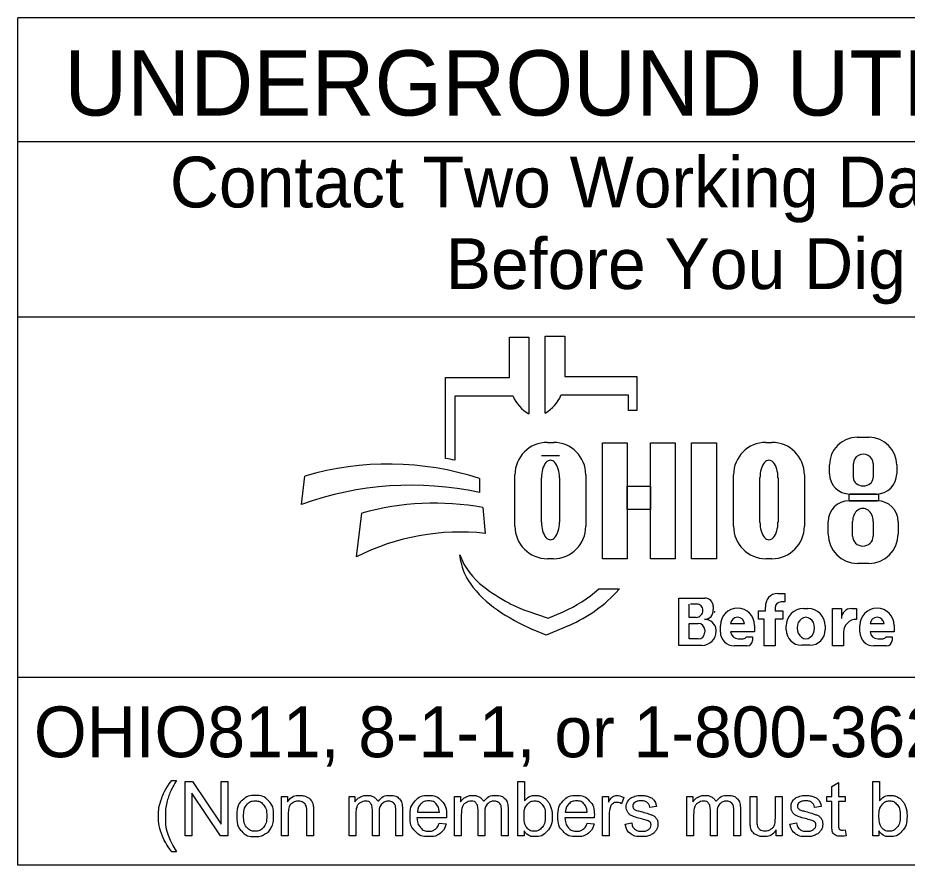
# Model space of a CAD drawing. Extents: x 39.5 to 73.5, y 15.6 to 37.6.
# Drawn here: x 42.479 to 44.932, y 18.55 to 20.887 of the extents above; entities that cross this region are included whole.
import ezdxf

# ---------------------------------------------------------------- set-up
doc = ezdxf.new("R2010")
doc.units = 0
doc.layers.add('GM_X_Interstate_Route', color=7, linetype='Continuous')
doc.layers.add('GM_X_Major_River_Text', color=7, linetype='Continuous')

msp = doc.modelspace()

# ---------------------------------------------------------------- linework, layer by layer
at = {"layer": 'GM_X_Interstate_Route'}
for p, q in [((43.8348, 19.8955), (43.8348, 20.0069)), ((43.8348, 20.0069), (43.8884, 20.0069)), ((43.8884, 20.0069), (43.8884, 19.7949)), ((43.9341, 19.7972), (43.9341, 20.0093)), ((43.9341, 20.0093), (43.9877, 20.0093)), ((43.9877, 20.0093), (43.9877, 19.8978)), ((43.6588, 19.6716), (43.6588, 19.8955)), ((43.6588, 19.8955), (43.8348, 19.8955)), ((43.9877, 19.8978), (44.187, 19.8978)), ((44.187, 19.8978), (44.187, 19.804)), ((43.684, 19.844), (43.684, 19.6672)), ((43.8452, 19.844), (43.684, 19.844)), ((44.1637, 19.8463), (43.9773, 19.8463)), ((44.1637, 19.804), (44.1637, 19.8463)), ((44.187, 19.804), (44.1637, 19.804)), ((44.7943, 19.7303), (44.8271, 19.7303)), ((43.9397, 19.7163), (43.9563, 19.7163)), ((44.5428, 19.7163), (44.5593, 19.7163)), ((43.973, 19.6793), (43.9232, 19.6793)), ((44.7842, 19.6183), (44.7842, 19.6576)), ((44.8383, 19.6576), (44.8383, 19.6183)), ((44.718, 19.6297), (44.718, 19.654)), ((44.9034, 19.654), (44.9034, 19.6297)), ((43.2614, 19.5453), (43.2708, 19.6234)), ((43.7521, 19.6169), (43.7521, 19.5781)), ((43.8503, 19.4848), (43.8503, 19.6268)), ((43.9232, 19.4962), (43.9232, 19.6185)), ((43.973, 19.6185), (43.973, 19.4962)), ((44.0458, 19.6268), (44.0458, 19.4848)), ((44.4533, 19.4848), (44.4533, 19.6268)), ((44.5262, 19.4962), (44.5262, 19.6185)), ((44.576, 19.6185), (44.576, 19.4962)), ((44.6488, 19.6268), (44.6488, 19.4848)), ((44.8474, 19.5737), (44.774, 19.5737)), ((43.7621, 19.5363), (43.7683, 19.4653)), ((44.7722, 19.5554), (44.8495, 19.5554)), ((43.4133, 19.4007), (43.4279, 19.5209)), ((44.7143, 19.4634), (44.7143, 19.4975)), ((44.7818, 19.4575), (44.7818, 19.4984)), ((44.8387, 19.4984), (44.8387, 19.4575)), ((44.9074, 19.4975), (44.9074, 19.4634)), ((43.7009, 19.3878), (43.6979, 19.4058)), ((43.9563, 19.3953), (43.9397, 19.3953)), ((44.5593, 19.3953), (44.5428, 19.3953)), ((44.8265, 19.3825), (44.7953, 19.3825)), ((44.0812, 19.312), (44.1387, 19.312)), ((44.3025, 19.1562), (44.3025, 19.2869)), ((44.3025, 19.2869), (44.3737, 19.2869)), ((44.5751, 19.2997), (44.5946, 19.2997)), ((44.5946, 19.2997), (44.5946, 19.2767)), ((44.3305, 19.2334), (44.3305, 19.2704)), ((44.3557, 19.2704), (44.3344, 19.2704)), ((44.3975, 19.2632), (44.3975, 19.2553)), ((44.5946, 19.2763), (44.5844, 19.2763)), ((43.8828, 19.2516), (43.9422, 19.2311)), ((43.9422, 19.2311), (43.9833, 19.2489)), ((44.5225, 19.2284), (44.5225, 19.2513)), ((44.5225, 19.2513), (44.5418, 19.2513)), ((44.5418, 19.2513), (44.5418, 19.2618)), ((44.5679, 19.2598), (44.5679, 19.2513)), ((44.5679, 19.2513), (44.5895, 19.2513)), ((44.5895, 19.2513), (44.5895, 19.2284)), ((44.6463, 19.2579), (44.6585, 19.2579)), ((44.7266, 19.155), (44.7266, 19.2577)), ((44.7266, 19.2577), (44.7511, 19.2577)), ((44.7511, 19.2577), (44.7511, 19.2308)), ((44.7784, 19.2577), (44.7923, 19.2577)), ((44.7923, 19.2577), (44.7923, 19.228)), ((44.3499, 19.2334), (44.3305, 19.2334)), ((44.3305, 19.174), (44.3305, 19.2169)), ((44.3305, 19.2169), (44.356, 19.2169)), ((44.4837, 19.2154), (44.4451, 19.2154)), ((44.5374, 19.2284), (44.5225, 19.2284)), ((44.5374, 19.155), (44.5374, 19.2284)), ((44.5895, 19.2284), (44.5679, 19.2284)), ((44.5679, 19.2284), (44.5679, 19.155)), ((44.8686, 19.2154), (44.8301, 19.2154)), ((43.9362, 19.1841), (43.8989, 19.2005)), ((43.9995, 19.2115), (43.9362, 19.1841)), ((44.3742, 19.1988), (44.3742, 19.1924)), ((44.4055, 19.1959), (44.4055, 19.1955)), ((44.4171, 19.193), (44.4171, 19.2114)), ((44.5116, 19.1937), (44.4452, 19.1937)), ((44.5116, 19.2114), (44.5116, 19.1937)), ((44.5985, 19.1993), (44.5985, 19.2101)), ((44.7063, 19.2101), (44.7063, 19.1993)), ((44.7571, 19.1931), (44.7571, 19.155)), ((44.802, 19.193), (44.802, 19.2114)), ((44.8965, 19.1937), (44.8301, 19.1937)), ((44.8965, 19.2114), (44.8965, 19.1937)), ((44.3558, 19.174), (44.3305, 19.174)), ((44.4661, 19.1745), (44.4802, 19.1745)), ((44.4888, 19.18), (44.5057, 19.18)), ((44.5057, 19.18), (44.5057, 19.1702)), ((44.851, 19.1745), (44.8652, 19.1745)), ((44.8737, 19.18), (44.8906, 19.18)), ((44.8906, 19.18), (44.8906, 19.1702)), ((44.3662, 19.1562), (44.3025, 19.1562)), ((44.4904, 19.155), (44.455, 19.155)), ((44.5679, 19.155), (44.5374, 19.155)), ((44.6635, 19.1565), (44.6413, 19.1565)), ((44.7571, 19.155), (44.7266, 19.155)), ((44.8754, 19.155), (44.84, 19.155))]:
    msp.add_line(p, q, dxfattribs=at)
for points in [[(44.0922, 19.7152), (44.1601, 19.7152), (44.1601, 19.3952), (44.0922, 19.3952)], [(44.2243, 19.7152), (44.2923, 19.7152), (44.2923, 19.3952), (44.2243, 19.3952)], [(44.3376, 19.7152), (44.4064, 19.7152), (44.4064, 19.3952), (44.3376, 19.3952)], [(44.1601, 19.5953), (44.2243, 19.5953), (44.2243, 19.5313), (44.1601, 19.5313)], [(44.7719, 19.5737), (44.8535, 19.5737), (44.8535, 19.5552), (44.7719, 19.5552)]]:
    msp.add_lwpolyline(points, close=True, dxfattribs=at)
for points in [[(42.9033, 18.7837), (42.9165, 18.7837)], [(42.9401, 18.6311), (42.9401, 18.7812), (42.9604, 18.7812), (43.0394, 18.6633), (43.0394, 18.7812), (43.0584, 18.7812), (43.0584, 18.6311), (43.0381, 18.6311), (42.9591, 18.749), (42.9591, 18.6311), (42.9401, 18.6311)], [(43.8755, 18.6311), (43.8585, 18.6311), (43.8585, 18.7812), (43.8769, 18.7812), (43.8769, 18.7277)], [(44.7245, 18.6629), (44.7245, 18.7256), (44.7109, 18.7256), (44.7109, 18.7399), (44.7245, 18.7399), (44.7245, 18.7669), (44.7429, 18.7779), (44.7429, 18.7399), (44.7613, 18.7399), (44.7613, 18.7256), (44.7429, 18.7256), (44.7429, 18.6618)], [(44.8546, 18.6311), (44.8376, 18.6311), (44.8376, 18.7812), (44.856, 18.7812), (44.856, 18.7277)], [(43.206, 18.6311), (43.206, 18.7399), (43.2226, 18.7399), (43.2226, 18.7244)], [(43.3925, 18.6311), (43.3925, 18.7399), (43.4089, 18.7399), (43.4089, 18.7246)], [(43.6838, 18.6311), (43.6838, 18.7399), (43.7003, 18.7399), (43.7003, 18.7246)], [(44.0916, 18.6311), (44.0916, 18.7399), (44.1082, 18.7399), (44.1082, 18.7234)], [(44.1507, 18.7364), (44.1442, 18.7194)], [(44.3248, 18.6311), (44.3248, 18.7399), (44.3413, 18.7399), (44.3413, 18.7246)], [(44.4991, 18.6725), (44.4991, 18.7399), (44.5176, 18.7399), (44.5176, 18.6796)], [(44.5688, 18.6816), (44.5688, 18.7399), (44.5873, 18.7399), (44.5873, 18.6311), (44.5708, 18.6311)], [(43.2944, 18.698), (43.2944, 18.6311), (43.276, 18.6311), (43.276, 18.6972)], [(43.4755, 18.6942), (43.4755, 18.6311), (43.4571, 18.6311), (43.4571, 18.7017)], [(43.54, 18.7057), (43.54, 18.6311), (43.5215, 18.6311), (43.5215, 18.6996)], [(43.7669, 18.6942), (43.7669, 18.6311), (43.7485, 18.6311), (43.7485, 18.7017)], [(43.8313, 18.7057), (43.8313, 18.6311), (43.8129, 18.6311), (43.8129, 18.6996)], [(44.2406, 18.7118), (44.2225, 18.7094)], [(44.4079, 18.6942), (44.4079, 18.6311), (44.3895, 18.6311), (44.3895, 18.7017)], [(44.4723, 18.7057), (44.4723, 18.6311), (44.4539, 18.6311), (44.4539, 18.6996)], [(44.6952, 18.7118), (44.6771, 18.7094)], [(43.2245, 18.6905), (43.2245, 18.6311), (43.206, 18.6311)], [(43.4109, 18.6875), (43.4109, 18.6311), (43.3925, 18.6311)], [(43.6612, 18.6807), (43.58, 18.6807)], [(43.5811, 18.6959), (43.6418, 18.6959)], [(43.7023, 18.6875), (43.7023, 18.6311), (43.6838, 18.6311)], [(44.0692, 18.6807), (43.988, 18.6807)], [(43.9891, 18.6959), (44.0498, 18.6959)], [(44.11, 18.6881), (44.11, 18.6311), (44.0916, 18.6311)], [(44.3433, 18.6875), (44.3433, 18.6311), (44.3248, 18.6311)], [(43.6416, 18.6662), (43.6607, 18.6638)], [(44.0496, 18.6662), (44.0687, 18.6638)], [(44.1542, 18.6636), (44.1724, 18.6664)], [(44.6088, 18.6636), (44.627, 18.6664)], [(43.8755, 18.6447), (43.8755, 18.6311)], [(44.5708, 18.6311), (44.5708, 18.6471)], [(44.7613, 18.6475), (44.764, 18.6312)], [(44.8546, 18.6447), (44.8546, 18.6311)], [(42.9165, 18.5869), (42.9033, 18.5869)]]:
    msp.add_lwpolyline(points, dxfattribs=at)
for centre, radius, start, end in [((43.9365, 19.8808), 0.0985, 201.9296, 240.7469), ((43.8859, 19.8831), 0.0985, 299.2531, 338.0704), ((44.7943, 19.654), 0.0763, 90, 180), ((44.8271, 19.654), 0.0763, 0, 90), ((43.9397, 19.6268), 0.0895, 90, 180), ((43.9563, 19.6268), 0.0895, 0, 90), ((44.5428, 19.6268), 0.0895, 90, 180), ((44.5593, 19.6268), 0.0895, 0, 90), ((43.5009, 18.8373), 0.8191, 72.1402, 106.3144), ((43.5307, 18.8626), 0.8191, 79.2074, 81.0007), ((44.774, 19.6297), 0.056, 180, 270), ((44.8474, 19.6297), 0.056, 270, 0), ((43.564, 18.7062), 0.8919, 77.8238, 109.8274), ((43.6279, 18.8165), 0.7322, 79.44, 105.8467), ((44.7722, 19.4975), 0.0579, 90, 180), ((44.8495, 19.4975), 0.0579, 0, 90), ((43.9397, 19.4848), 0.0895, 180, 270), ((43.9563, 19.4848), 0.0895, 270, 0), ((44.5428, 19.4848), 0.0895, 180, 270), ((44.5593, 19.4848), 0.0895, 270, 0), ((43.6999, 18.8333), 0.6357, 83.8248, 116.8021), ((44.7953, 19.4634), 0.081, 180, 270), ((44.8265, 19.4634), 0.081, 270, 0), ((43.8853, 19.4779), 0.2008, 201.0457, 232.5314), ((43.8422, 19.4119), 0.1433, 189.6817, 216.0884), ((43.9759, 19.5094), 0.3088, 216.0884, 235.7167), ((44.0778, 19.7291), 0.5173, 232.5314, 241.794), ((43.8399, 19.5794), 0.3602, 293.4582, 312.0712), ((43.8399, 19.5794), 0.401, 293.4582, 317.8286), ((44.3737, 19.2632), 0.0238, 0, 90), ((44.5751, 19.2662), 0.0335, 90, 187.5187), ((43.9926, 19.5703), 0.3371, 241.794, 250.9821), ((44.3518, 19.2535), 0.0169, 357.8325, 90), ((44.5844, 19.2598), 0.0165, 90, 180), ((44.1424, 19.7536), 0.6044, 235.7167, 246.2325), ((44.3499, 19.2522), 0.0187, 270, 2.0582), ((44.3733, 19.2524), 0.0243, 270, 6.6529), ((44.3839, 19.251), 0.0175, 347.4023, 0), ((44.4643, 19.2114), 0.0473, 0, 180), ((44.6463, 19.2101), 0.0478, 90, 180), ((44.6585, 19.2101), 0.0478, 0, 90), ((44.778, 19.2308), 0.0269, 89.2449, 180), ((44.8493, 19.2114), 0.0473, 0, 180), ((44.356, 19.1988), 0.0181, 0, 90), ((44.3734, 19.196), 0.0321, 4.0748, 90), ((44.4644, 19.2144), 0.0193, 2.9632, 177.0368), ((44.792, 19.1931), 0.0349, 89.6033, 180), ((44.8493, 19.2144), 0.0193, 2.9632, 177.0368), ((44.3558, 19.1924), 0.0184, 270, 0), ((44.3662, 19.1955), 0.0393, 270, 0), ((44.3726, 19.1959), 0.033, 0, 11.7502), ((44.455, 19.193), 0.038, 180, 270), ((44.4661, 19.1955), 0.021, 184.827, 270), ((44.6413, 19.1993), 0.0428, 180, 270), ((44.6635, 19.1993), 0.0428, 270, 0), ((44.84, 19.193), 0.038, 180, 270), ((44.851, 19.1955), 0.021, 184.827, 270), ((44.4802, 19.1839), 0.00938, 270, 335.9979), ((44.4904, 19.1702), 0.0152, 270, 0), ((44.8652, 19.1839), 0.00938, 270, 335.9979), ((44.8754, 19.1702), 0.0152, 270, 0)]:
    msp.add_arc(centre, radius, start, end, dxfattribs=at)
for centre, major_axis, ratio, start_param, end_param in [((44.8112, 19.6576), (0.0271, 0), 0.969373, 0, 3.141593), ((43.9481, 19.6185), (0, 0.0484), 0.514403, 4.712389, 7.853982), ((44.5511, 19.6185), (0, 0.0484), 0.514403, 4.712389, 7.853982), ((44.8112, 19.6183), (0.0271, 0), 0.818453, 3.141593, 6.283185), ((44.8102, 19.4984), (0, 0.0358), 0.794529, 4.712389, 7.853982), ((43.9481, 19.4962), (0, 0.0484), 0.514403, 1.570796, 4.712389), ((44.5511, 19.4962), (0, 0.0484), 0.514403, 1.570796, 4.712389), ((44.8102, 19.4575), (0.0284, 0), 0.959837, 3.141593, 6.283185), ((44.6529, 19.2047), (0, 0.029), 0.832186, 4.712389, 7.853982), ((44.6529, 19.2047), (0, 0.0302), 0.797287, 1.570796, 4.712389)]:
    msp.add_ellipse(centre, major_axis=major_axis, ratio=ratio, start_param=start_param, end_param=end_param, dxfattribs=at)
for points in [[(42.9033, 18.5869), (42.8881, 18.6062), (42.8775, 18.632), (42.8669, 18.6578), (42.8669, 18.6854), (42.8669, 18.7098), (42.8748, 18.7321), (42.8841, 18.758), (42.9033, 18.7837)], [(42.9165, 18.7837), (42.9041, 18.7624), (42.9002, 18.7533), (42.8939, 18.7392), (42.8903, 18.7238), (42.8859, 18.7047), (42.8859, 18.6853), (42.8859, 18.6361), (42.9165, 18.5869)], [(43.0826, 18.6855), (43.0826, 18.7157), (43.0993, 18.7302), (43.1134, 18.7423), (43.1335, 18.7423), (43.156, 18.7423), (43.1702, 18.7276), (43.1844, 18.7129), (43.1844, 18.687), (43.1844, 18.666), (43.1781, 18.654), (43.1718, 18.642), (43.1598, 18.6353), (43.1478, 18.6287), (43.1335, 18.6287), (43.1107, 18.6287), (43.0966, 18.6433), (43.0826, 18.658), (43.0826, 18.6855)], [(43.1016, 18.6855), (43.1016, 18.6646), (43.1107, 18.6542), (43.1197, 18.6438), (43.1335, 18.6438), (43.1472, 18.6438), (43.1563, 18.6542), (43.1654, 18.6647), (43.1654, 18.6861), (43.1654, 18.7063), (43.1563, 18.7167), (43.1471, 18.7271), (43.1335, 18.7271), (43.1197, 18.7271), (43.1107, 18.7167), (43.1016, 18.7064), (43.1016, 18.6855)], [(43.2226, 18.7244), (43.2346, 18.7423), (43.2572, 18.7423), (43.2671, 18.7423), (43.2753, 18.7388), (43.2835, 18.7352), (43.2876, 18.7295), (43.2917, 18.7238), (43.2934, 18.7159), (43.2944, 18.7108), (43.2944, 18.698)], [(43.276, 18.6972), (43.276, 18.7085), (43.2738, 18.7141), (43.2717, 18.7196), (43.2662, 18.723), (43.2607, 18.7263), (43.2533, 18.7263), (43.2416, 18.7263), (43.233, 18.7188), (43.2245, 18.7113), (43.2245, 18.6905)], [(43.4089, 18.7246), (43.4141, 18.7326), (43.4226, 18.7374), (43.4311, 18.7423), (43.4419, 18.7423), (43.454, 18.7423), (43.4618, 18.7373), (43.4695, 18.7323), (43.4727, 18.7232), (43.4856, 18.7423), (43.5063, 18.7423), (43.5225, 18.7423), (43.5313, 18.7334), (43.54, 18.7244), (43.54, 18.7057)], [(43.4571, 18.7017), (43.4571, 18.714), (43.4526, 18.7202), (43.4481, 18.7263), (43.4378, 18.7263), (43.4301, 18.7263), (43.4234, 18.7222), (43.4168, 18.7181), (43.4139, 18.7102), (43.4109, 18.7023), (43.4109, 18.6875)], [(43.5215, 18.6996), (43.5215, 18.7106), (43.5198, 18.7155), (43.518, 18.7204), (43.5132, 18.7233), (43.5085, 18.7263), (43.5022, 18.7263), (43.4907, 18.7263), (43.4831, 18.7187), (43.4755, 18.711), (43.4755, 18.6942)], [(43.6607, 18.6638), (43.6562, 18.6471), (43.644, 18.6379), (43.6318, 18.6287), (43.6129, 18.6287), (43.589, 18.6287), (43.575, 18.6434), (43.561, 18.6581), (43.561, 18.6846), (43.561, 18.712), (43.5752, 18.7272), (43.5893, 18.7423), (43.6118, 18.7423), (43.6337, 18.7423), (43.6475, 18.7275), (43.6613, 18.7126), (43.6613, 18.6857), (43.6613, 18.684), (43.6612, 18.6807)], [(43.6418, 18.6959), (43.6406, 18.7096), (43.6349, 18.7165), (43.6261, 18.7272), (43.612, 18.7272), (43.5993, 18.7272), (43.5907, 18.7187), (43.582, 18.7101), (43.5811, 18.6959)], [(43.7003, 18.7246), (43.7054, 18.7326), (43.7139, 18.7374), (43.7224, 18.7423), (43.7333, 18.7423), (43.7454, 18.7423), (43.7531, 18.7373), (43.7609, 18.7323), (43.764, 18.7232), (43.777, 18.7423), (43.7977, 18.7423), (43.8139, 18.7423), (43.8226, 18.7334), (43.8313, 18.7244), (43.8313, 18.7057)], [(43.7485, 18.7017), (43.7485, 18.714), (43.744, 18.7202), (43.7395, 18.7263), (43.7292, 18.7263), (43.7214, 18.7263), (43.7148, 18.7222), (43.7082, 18.7181), (43.7052, 18.7102), (43.7023, 18.7023), (43.7023, 18.6875)], [(43.8129, 18.6996), (43.8129, 18.7106), (43.8111, 18.7155), (43.8093, 18.7204), (43.8046, 18.7233), (43.7999, 18.7263), (43.7936, 18.7263), (43.7821, 18.7263), (43.7745, 18.7187), (43.7669, 18.711), (43.7669, 18.6942)], [(43.8753, 18.6863), (43.8753, 18.6667), (43.8806, 18.658), (43.8893, 18.6438), (43.9041, 18.6438), (43.9162, 18.6438), (43.925, 18.6543), (43.9338, 18.6648), (43.9338, 18.6856), (43.9338, 18.7069), (43.9254, 18.7171), (43.9169, 18.7272), (43.905, 18.7272), (43.8929, 18.7272), (43.8841, 18.7167), (43.8753, 18.7062), (43.8753, 18.6863)], [(43.8769, 18.7277), (43.8886, 18.7423), (43.9067, 18.7423), (43.9167, 18.7423), (43.9257, 18.7383), (43.9347, 18.7342), (43.9405, 18.7269), (43.9462, 18.7196), (43.9495, 18.7092), (43.9528, 18.6989), (43.9528, 18.6871), (43.9528, 18.6592), (43.939, 18.6439), (43.9251, 18.6287), (43.9058, 18.6287), (43.8865, 18.6287), (43.8755, 18.6447)], [(44.0687, 18.6638), (44.0642, 18.6471), (44.052, 18.6379), (44.0398, 18.6287), (44.0209, 18.6287), (43.997, 18.6287), (43.983, 18.6434), (43.969, 18.6581), (43.969, 18.6846), (43.969, 18.712), (43.9832, 18.7272), (43.9973, 18.7423), (44.0198, 18.7423), (44.0416, 18.7423), (44.0555, 18.7275), (44.0693, 18.7126), (44.0693, 18.6857), (44.0693, 18.684), (44.0692, 18.6807)], [(44.0498, 18.6959), (44.0486, 18.7096), (44.0429, 18.7165), (44.0341, 18.7272), (44.02, 18.7272), (44.0073, 18.7272), (43.9987, 18.7187), (43.99, 18.7101), (43.9891, 18.6959)], [(44.1082, 18.7234), (44.1145, 18.735), (44.1199, 18.7386), (44.1253, 18.7423), (44.1317, 18.7423), (44.141, 18.7423), (44.1507, 18.7364)], [(44.1442, 18.7194), (44.1375, 18.7233), (44.1308, 18.7233), (44.1247, 18.7233), (44.1199, 18.7197), (44.1152, 18.716), (44.1131, 18.7096), (44.11, 18.6997), (44.11, 18.6881)], [(44.2225, 18.7094), (44.2213, 18.7178), (44.2154, 18.7225), (44.2095, 18.7272), (44.1987, 18.7272), (44.186, 18.7272), (44.1806, 18.723), (44.1752, 18.7188), (44.1752, 18.7132), (44.1752, 18.7096), (44.1774, 18.7067), (44.1797, 18.7037), (44.1845, 18.7018), (44.1873, 18.7007), (44.2008, 18.697), (44.2204, 18.6918), (44.2281, 18.6885), (44.2359, 18.6852), (44.2403, 18.6788), (44.2447, 18.6725), (44.2447, 18.6631), (44.2447, 18.6539), (44.2393, 18.6457), (44.234, 18.6376), (44.2238, 18.6331), (44.2136, 18.6287), (44.2008, 18.6287), (44.1796, 18.6287), (44.1684, 18.6375), (44.1573, 18.6463), (44.1542, 18.6636)], [(44.1724, 18.6664), (44.1739, 18.6555), (44.181, 18.6496), (44.188, 18.6438), (44.2007, 18.6438), (44.2134, 18.6438), (44.2196, 18.649), (44.2257, 18.6541), (44.2257, 18.6611), (44.2257, 18.6674), (44.2203, 18.671), (44.2165, 18.6734), (44.2014, 18.6772), (44.1811, 18.6823), (44.1733, 18.6861), (44.1654, 18.6898), (44.1614, 18.6964), (44.1573, 18.703), (44.1573, 18.711), (44.1573, 18.7183), (44.1606, 18.7245), (44.164, 18.7306), (44.1697, 18.7347), (44.174, 18.7379), (44.1815, 18.7401), (44.1889, 18.7423), (44.1974, 18.7423), (44.2102, 18.7423), (44.2199, 18.7386), (44.2296, 18.7349), (44.2343, 18.7286), (44.2389, 18.7223), (44.2406, 18.7118)], [(44.3413, 18.7246), (44.3464, 18.7326), (44.3549, 18.7374), (44.3634, 18.7423), (44.3743, 18.7423), (44.3864, 18.7423), (44.3941, 18.7373), (44.4019, 18.7323), (44.405, 18.7232), (44.418, 18.7423), (44.4387, 18.7423), (44.4549, 18.7423), (44.4636, 18.7334), (44.4723, 18.7244), (44.4723, 18.7057)], [(44.3895, 18.7017), (44.3895, 18.714), (44.385, 18.7202), (44.3805, 18.7263), (44.3702, 18.7263), (44.3624, 18.7263), (44.3558, 18.7222), (44.3492, 18.7181), (44.3462, 18.7102), (44.3433, 18.7023), (44.3433, 18.6875)], [(44.4539, 18.6996), (44.4539, 18.7106), (44.4521, 18.7155), (44.4503, 18.7204), (44.4456, 18.7233), (44.4409, 18.7263), (44.4346, 18.7263), (44.4231, 18.7263), (44.4155, 18.7187), (44.4079, 18.711), (44.4079, 18.6942)], [(44.6771, 18.7094), (44.6759, 18.7178), (44.67, 18.7225), (44.6641, 18.7272), (44.6533, 18.7272), (44.6406, 18.7272), (44.6352, 18.723), (44.6297, 18.7188), (44.6297, 18.7132), (44.6297, 18.7096), (44.632, 18.7067), (44.6342, 18.7037), (44.6391, 18.7018), (44.6418, 18.7007), (44.6554, 18.697), (44.675, 18.6918), (44.6827, 18.6885), (44.6905, 18.6852), (44.6949, 18.6788), (44.6993, 18.6725), (44.6993, 18.6631), (44.6993, 18.6539), (44.6939, 18.6457), (44.6885, 18.6376), (44.6784, 18.6331), (44.6682, 18.6287), (44.6554, 18.6287), (44.6341, 18.6287), (44.623, 18.6375), (44.6119, 18.6463), (44.6088, 18.6636)], [(44.627, 18.6664), (44.6285, 18.6555), (44.6356, 18.6496), (44.6426, 18.6438), (44.6552, 18.6438), (44.668, 18.6438), (44.6741, 18.649), (44.6803, 18.6541), (44.6803, 18.6611), (44.6803, 18.6674), (44.6749, 18.671), (44.6711, 18.6734), (44.656, 18.6772), (44.6357, 18.6823), (44.6278, 18.6861), (44.62, 18.6898), (44.6159, 18.6964), (44.6119, 18.703), (44.6119, 18.711), (44.6119, 18.7183), (44.6152, 18.7245), (44.6185, 18.7306), (44.6243, 18.7347), (44.6286, 18.7379), (44.636, 18.7401), (44.6435, 18.7423), (44.652, 18.7423), (44.6648, 18.7423), (44.6745, 18.7386), (44.6842, 18.7349), (44.6888, 18.7286), (44.6934, 18.7223), (44.6952, 18.7118)], [(44.8544, 18.6863), (44.8544, 18.6667), (44.8597, 18.658), (44.8684, 18.6438), (44.8832, 18.6438), (44.8953, 18.6438), (44.9041, 18.6543), (44.9129, 18.6648), (44.9129, 18.6856), (44.9129, 18.7069), (44.9044, 18.7171), (44.896, 18.7272), (44.884, 18.7272), (44.872, 18.7272), (44.8632, 18.7167), (44.8544, 18.7062), (44.8544, 18.6863)], [(44.856, 18.7277), (44.8677, 18.7423), (44.8858, 18.7423), (44.8958, 18.7423), (44.9048, 18.7383), (44.9137, 18.7342), (44.9195, 18.7269), (44.9253, 18.7196), (44.9286, 18.7092), (44.9319, 18.6989), (44.9319, 18.6871), (44.9319, 18.6592), (44.918, 18.6439), (44.9042, 18.6287), (44.8848, 18.6287), (44.8656, 18.6287), (44.8546, 18.6447)], [(43.58, 18.6807), (43.5811, 18.6628), (43.5902, 18.6533), (43.5993, 18.6438), (43.6129, 18.6438), (43.6231, 18.6438), (43.6303, 18.6491), (43.6374, 18.6545), (43.6416, 18.6662)], [(43.988, 18.6807), (43.9891, 18.6628), (43.9982, 18.6533), (44.0073, 18.6438), (44.0209, 18.6438), (44.0311, 18.6438), (44.0383, 18.6491), (44.0454, 18.6545), (44.0496, 18.6662)], [(44.5176, 18.6796), (44.5176, 18.6652), (44.5187, 18.6601), (44.5204, 18.6529), (44.5261, 18.6487), (44.5317, 18.6446), (44.54, 18.6446), (44.5483, 18.6446), (44.5555, 18.6488), (44.5628, 18.6531), (44.5658, 18.6604), (44.5688, 18.6677), (44.5688, 18.6816)], [(44.5708, 18.6471), (44.5581, 18.6287), (44.5363, 18.6287), (44.5267, 18.6287), (44.5183, 18.6324), (44.51, 18.636), (44.5059, 18.6416), (44.5019, 18.6472), (44.5003, 18.6553), (44.4991, 18.6607), (44.4991, 18.6725)], [(44.764, 18.6312), (44.7562, 18.6296), (44.7501, 18.6296), (44.74, 18.6296), (44.7345, 18.6328), (44.729, 18.6359), (44.7267, 18.6411), (44.7245, 18.6463), (44.7245, 18.6629)], [(44.7429, 18.6618), (44.7429, 18.6539), (44.7439, 18.6517), (44.7448, 18.6494), (44.747, 18.6481), (44.7492, 18.6468), (44.7533, 18.6468), (44.7563, 18.6468), (44.7613, 18.6475)]]:
    msp.add_open_spline(points, degree=3, dxfattribs=at)
at = {"layer": 'GM_X_Major_River_Text'}
for p, q in [((42.4787, 18.5499), (42.4787, 20.8874)), ((46.7287, 20.8874), (42.4787, 20.8874)), ((42.4787, 20.5459), (46.7287, 20.5459)), ((42.4787, 20.0625), (46.7287, 20.0625)), ((46.7287, 19.0678), (42.4787, 19.0678)), ((46.7287, 18.5499), (42.4787, 18.5499))]:
    msp.add_line(p, q, dxfattribs=at)

# ---------------------------------------------------------------- texts
at = {"layer": 'GM_X_Interstate_Route'}
for s, height, p in [('UNDERGROUND UTILITIES', 0.18, (42.6069, 20.6178)), ('Contact Two Working Days', 0.14, (42.8984, 20.3643)), ('Before You Dig', 0.14, (43.6595, 20.1393)), ('OHIO811, 8-1-1, or 1-800-362-2764', 0.14, (42.5232, 18.8478))]:
    msp.add_text(s, height=height, dxfattribs=at).set_placement(p)

doc.saveas('drawing.dxf')
